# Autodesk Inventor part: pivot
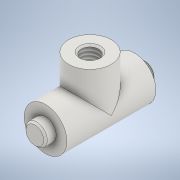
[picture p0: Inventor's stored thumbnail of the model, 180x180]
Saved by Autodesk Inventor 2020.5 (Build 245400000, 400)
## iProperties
Created: 2022-10
Part Number: pivot
Material: Acier, non allié
Document SubType Name: Modeling
Designer: mel
Density: 7.85 g/cm^3
Appearance: Acier
Author: mel
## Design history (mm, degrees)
sketch "Esquisse1"
  geometry: C1 r 6 at (0, 0); 1 further point
  constraints: 1 centre point, 1 coincident
  dimensions: "d0" = 12 diameter of C1
extrude "Extrusion1" new body sketch "Esquisse1" stored distance "d1" = 25; taper "d2" = 0 deg
sketch "Esquisse2"
  geometry: C1 r 6 at (0, 0); 1 further point
  constraints: 1 centre point, 1 coincident
extrude "Extrusion2" join sketch "Esquisse2" distance "d3" = 12.5; taper "d4" = 0 deg
sketch "Esquisse3"
  geometry: C1 r 3 at (0, 0); 1 further point
  constraints: 1 centre point, 1 coincident
  dimensions: "d5" = 6 diameter of C1
extrude "Extrusion3" join sketch "Esquisse3" distance "d6" = 3; taper "d7" = 0 deg
mirror "Symétrie1"
sketch "Esquisse4"
  geometry: 2 further points
  constraints: 1 coincident
hole "Perçage1" sketch "Esquisse4" at (0, 0) diameter "d8" = 4.917; stored, may be unused: countersink angle "d12" = 90 deg, drill point angle "d14" = 118 deg; dims "d9" = 8, "d10" = 4, "d11" = 2, "d13" = 12
chamfer "Chanfrein1" distance "d15" = 0.5; stored, may be unused: second distance "d16" = 2, angle "d17" = 45 deg
chamfer "Chanfrein2" distance "d18" = 0.5; stored, may be unused: second distance "d19" = 2, angle "d20" = 45 deg
node "Solide1"
